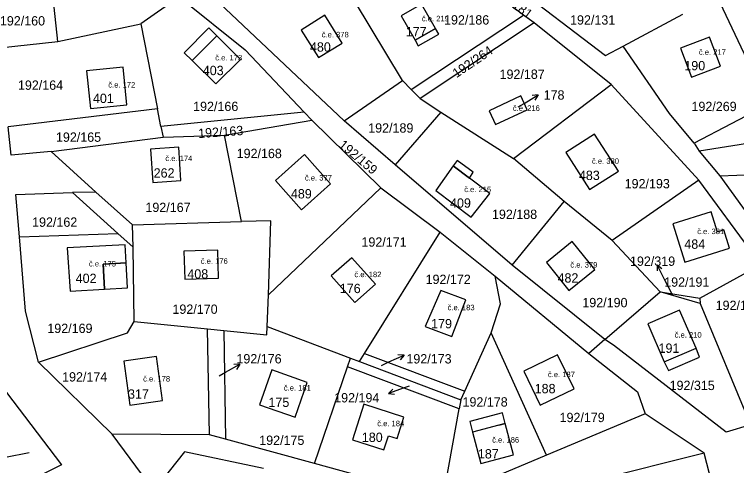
# Model space of a CAD drawing. Extents: x -887272 to -880188, y -1026687 to -1021896.
# Drawn here: x -882333.3 to -882201.9, y -1024194 to -1024111.9 of the extents above; entities that cross this region are included whole.
import ezdxf

# ---------------------------------------------------------------- set-up
doc = ezdxf.new("R2010")
doc.units = 0
for name, color, linetype in [('Definiční body', 7, 'Continuous'), ('Hranice parcel', 7, 'Continuous'), ('Parcelní čísla', 7, 'Continuous'), ('Polygon budovy', 7, 'Continuous'), ('Pop  PČ popisy', 7, 'Continuous'), ('Vnitřní kresba', 7, 'Continuous')]:
    doc.layers.add(name, color=color, linetype=linetype)

msp = doc.modelspace()

# ---------------------------------------------------------------- linework, layer by layer
at = {"layer": 'Hranice parcel'}
for p, q in [((-882240.6, -1024111.96), (-882256.19, -1024100.43)), ((-882325.37, -1024116.79), (-882326.44, -1024106.78)), ((-882273.27, -1024131.24), (-882298.33, -1024107.54)), ((-882303.23, -1024108.62), (-882310.26, -1024113.56)), ((-882262.64, -1024123.91), (-882271.37, -1024109.4)), ((-882261.07, -1024125.53), (-882240.6, -1024111.96)), ((-882238.67, -1024113.39), (-882240.6, -1024111.96)), ((-882222.5, -1024117.62), (-882211.61, -1024111.8)), ((-882325.37, -1024116.79), (-882310.26, -1024113.56)), ((-882310.26, -1024113.56), (-882307.23, -1024129.06)), ((-882238.67, -1024113.39), (-882259.45, -1024127.19)), ((-882224.7, -1024124.59), (-882238.67, -1024113.39)), ((-882336.02, -1024117.94), (-882325.37, -1024116.79)), ((-882273.27, -1024131.24), (-882262.64, -1024123.91)), ((-882262.64, -1024123.91), (-882261.07, -1024125.53)), ((-882242.43, -1024138.12), (-882224.7, -1024124.59)), ((-882224.7, -1024124.59), (-882208.75, -1024142.05)), ((-882259.45, -1024127.19), (-882261.07, -1024125.53)), ((-882259.45, -1024127.19), (-882255.64, -1024129.63)), ((-882307.23, -1024129.06), (-882334.41, -1024132.3)), ((-882306.6, -1024132.25), (-882307.23, -1024129.06)), ((-882280.53, -1024129.66), (-882306.6, -1024132.25)), ((-882280.53, -1024129.66), (-882279.12, -1024131.14)), ((-882255.64, -1024129.63), (-882263.95, -1024139.24)), ((-882255.64, -1024129.63), (-882242.43, -1024138.12)), ((-882295.03, -1024133.84), (-882279.12, -1024131.14)), ((-882279.12, -1024131.14), (-882266.59, -1024143.44)), ((-882263.95, -1024139.24), (-882273.27, -1024131.24)), ((-882306.6, -1024132.25), (-882306.22, -1024134.21)), ((-882306.22, -1024134.21), (-882295.03, -1024133.84)), ((-882291.94, -1024149.59), (-882295.03, -1024133.84)), ((-882190.49, -1024133.91), (-882208.64, -1024136.73)), ((-882326.6, -1024136.81), (-882306.22, -1024134.21)), ((-882209.58, -1024135.28), (-882208.64, -1024136.73)), ((-882208.64, -1024136.73), (-882204.92, -1024141.27)), ((-882242.67, -1024157.52), (-882263.95, -1024139.24)), ((-882233.24, -1024145.95), (-882242.43, -1024138.12)), ((-882204.92, -1024141.27), (-882175.35, -1024139.88)), ((-882204.92, -1024141.27), (-882191.8, -1024159.41)), ((-882208.75, -1024142.05), (-882224.52, -1024153.03)), ((-882197.43, -1024157.42), (-882208.75, -1024142.05)), ((-882266.59, -1024143.44), (-882287.05, -1024162.93)), ((-882266.59, -1024143.44), (-882255.81, -1024151.5)), ((-882242.67, -1024157.52), (-882233.24, -1024145.95)), ((-882224.52, -1024153.03), (-882233.24, -1024145.95)), ((-882311.75, -1024150.18), (-882291.94, -1024149.59)), ((-882286.58, -1024149.42), (-882291.94, -1024149.59)), ((-882287.05, -1024162.93), (-882286.58, -1024149.42)), ((-882311.68, -1024154.26), (-882311.75, -1024150.18)), ((-882332.34, -1024152.38), (-882314.45, -1024151.74)), ((-882314.45, -1024151.74), (-882311.68, -1024154.26)), ((-882269.58, -1024173.58), (-882255.81, -1024151.5)), ((-882255.81, -1024151.5), (-882245.77, -1024159.53)), ((-882231.74, -1024153.22), (-882236.46, -1024157.01)), ((-882215.75, -1024162.36), (-882224.52, -1024153.03)), ((-882311.45, -1024167.77), (-882311.68, -1024154.26)), ((-882225.84, -1024171.07), (-882242.67, -1024157.52)), ((-882208.53, -1024163.52), (-882197.43, -1024157.42)), ((-882245.77, -1024159.53), (-882228.75, -1024173.58)), ((-882287.25, -1024168.71), (-882287.05, -1024162.93)), ((-882225.84, -1024171.07), (-882215.75, -1024162.36)), ((-882215.75, -1024162.36), (-882208.53, -1024163.52)), ((-882208.46, -1024164.48), (-882215.75, -1024162.36)), ((-882208.53, -1024163.52), (-882208.46, -1024164.48)), ((-882208.46, -1024164.48), (-882199.3, -1024186.6)), ((-882311.45, -1024167.77), (-882298.11, -1024169.12)), ((-882298.11, -1024169.12), (-882295.13, -1024169.42)), ((-882297.75, -1024188.41), (-882298.11, -1024169.12)), ((-882295.13, -1024169.42), (-882294.85, -1024189.2)), ((-882287.25, -1024168.71), (-882272.13, -1024174.43)), ((-882251.31, -1024180.47), (-882246.53, -1024169.84)), ((-882236.46, -1024192.13), (-882246.53, -1024169.84)), ((-882225.84, -1024171.07), (-882228.75, -1024173.58)), ((-882272.67, -1024176.01), (-882272.13, -1024174.43)), ((-882272.13, -1024174.43), (-882270.49, -1024175.04)), ((-882270.49, -1024175.04), (-882269.58, -1024173.58)), ((-882269.58, -1024173.58), (-882251.31, -1024180.47)), ((-882315.45, -1024188.28), (-882328.87, -1024175.2)), ((-882278.63, -1024193.63), (-882272.67, -1024176.01)), ((-882252.31, -1024183.68), (-882272.67, -1024176.01)), ((-882270.49, -1024175.04), (-882252.01, -1024182.03)), ((-882252.01, -1024182.03), (-882251.31, -1024180.47)), ((-882252.01, -1024182.03), (-882252.31, -1024183.68)), ((-882255.25, -1024200.01), (-882252.31, -1024183.68)), ((-882218.48, -1024184.59), (-882236.46, -1024192.13)), ((-882207.74, -1024191.74), (-882218.48, -1024184.59)), ((-882297.75, -1024188.41), (-882315.45, -1024188.28)), ((-882307.87, -1024198.55), (-882315.45, -1024188.28)), ((-882294.85, -1024189.2), (-882297.75, -1024188.41)), ((-882278.63, -1024193.63), (-882294.85, -1024189.2)), ((-882207.74, -1024191.74), (-882227.58, -1024196.72)), ((-882204.37, -1024205.08), (-882207.74, -1024191.74)), ((-882236.46, -1024192.13), (-882255.25, -1024200.01)), ((-882255.25, -1024200.01), (-882278.63, -1024193.63))]:
    msp.add_line(p, q, dxfattribs=at)
for points in [[(-882243.24, -1024105.91), (-882225.71, -1024119.34), (-882222.5, -1024117.62)], [(-882303.23, -1024108.62), (-882291.29, -1024118.32), (-882280.53, -1024129.66)], [(-882205.42, -1024108.48), (-882196.11, -1024128.27), (-882209.58, -1024135.28)], [(-882259.17, -1024109.96), (-882262.9, -1024112.1), (-882260.34, -1024116.56), (-882259.77, -1024117.56), (-882256.04, -1024115.42), (-882256.61, -1024114.42), (-882259.17, -1024109.96)], [(-882276.8, -1024112.01), (-882281.11, -1024114.74), (-882277.9, -1024119.72)], [(-882277.9, -1024119.72), (-882273.64, -1024117.11), (-882276.8, -1024112.01)], [(-882302.36, -1024118.83), (-882300.9, -1024120.27), (-882296.63, -1024124.49), (-882292.12, -1024120.06), (-882296.44, -1024115.78), (-882297.91, -1024114.32), (-882302.36, -1024118.83)], [(-882206.79, -1024115.98), (-882212.07, -1024117.99), (-882210.06, -1024123.27), (-882204.78, -1024121.26), (-882206.79, -1024115.98)], [(-882209.58, -1024135.28), (-882214.07, -1024129.89), (-882222.5, -1024117.62)], [(-882320.14, -1024122.11), (-882319.42, -1024128.99), (-882312.79, -1024128.33), (-882313.5, -1024121.45), (-882320.14, -1024122.11)], [(-882239.95, -1024129.23), (-882241.14, -1024126.7), (-882246.89, -1024129.39), (-882245.73, -1024131.88), (-882239.95, -1024129.23)], [(-882326.6, -1024136.81), (-882333.83, -1024137.51), (-882334.41, -1024132.3)], [(-882232.9, -1024136.97), (-882228.63, -1024143.71), (-882223.31, -1024140.39), (-882227.68, -1024133.67), (-882232.9, -1024136.97)], [(-882308.5, -1024136.4), (-882308.08, -1024142.48), (-882302.95, -1024142.12), (-882303.37, -1024136.04), (-882308.5, -1024136.4)], [(-882311.75, -1024150.18), (-882318.47, -1024144.2), (-882326.6, -1024136.81)], [(-882280.47, -1024137.35), (-882285.76, -1024142.1), (-882281.04, -1024147.43), (-882275.73, -1024142.69), (-882280.47, -1024137.35)], [(-882250.44, -1024141.66), (-882249.76, -1024140.6), (-882252.7, -1024138.44), (-882253.4, -1024139.42), (-882256.6, -1024143.89), (-882250.16, -1024148.8), (-882246.78, -1024144.44), (-882250.44, -1024141.66)], [(-882332.34, -1024152.38), (-882332.98, -1024144.63), (-882322.66, -1024144.28), (-882314.45, -1024151.74)], [(-882204.16, -1024151.1), (-882205.35, -1024151.48), (-882206.5, -1024147.81), (-882213.47, -1024149.97), (-882211.29, -1024156.96), (-882203.13, -1024154.43), (-882204.16, -1024151.1)], [(-882328.87, -1024175.2), (-882331.22, -1024165.89), (-882332.34, -1024152.38)], [(-882236.46, -1024157.01), (-882232.35, -1024162.12), (-882227.63, -1024158.33), (-882231.74, -1024153.22)], [(-882313.11, -1024153.8), (-882323.69, -1024154.38), (-882323.12, -1024162.22), (-882316.86, -1024161.9), (-882312.69, -1024161.65), (-882312.93, -1024157.1), (-882313.11, -1024153.8)], [(-882302.42, -1024154.94), (-882302.27, -1024160.04), (-882296.12, -1024159.86), (-882296.27, -1024154.76), (-882302.42, -1024154.94)], [(-882271.32, -1024164.34), (-882267.54, -1024160.98), (-882271.88, -1024156.18), (-882275.64, -1024159.48), (-882271.32, -1024164.34)], [(-882246.53, -1024169.84), (-882244.78, -1024164.57), (-882245.77, -1024159.53)], [(-882253.64, -1024170.5), (-882251.12, -1024163.82), (-882255.66, -1024162.1), (-882258.5, -1024168.66), (-882253.64, -1024170.5)], [(-882215.03, -1024175.11), (-882214.26, -1024176.72), (-882208.6, -1024174.25), (-882209.22, -1024172.63), (-882212.26, -1024165.7), (-882218.01, -1024168.17), (-882215.03, -1024175.11)], [(-882328.87, -1024175.2), (-882312.69, -1024169.82), (-882311.45, -1024167.77)], [(-882295.13, -1024169.42), (-882287.3, -1024170.21), (-882287.25, -1024168.71)], [(-882199.3, -1024186.6), (-882203.76, -1024187.9), (-882224.27, -1024172.09), (-882225.84, -1024171.07)], [(-882313.37, -1024174.98), (-882312.24, -1024183), (-882306.31, -1024182.16), (-882307.43, -1024174.15), (-882313.37, -1024174.98)], [(-882237.58, -1024183.02), (-882231.43, -1024180.03), (-882234.46, -1024173.84), (-882240.59, -1024176.84), (-882237.58, -1024183.02)], [(-882228.75, -1024173.58), (-882219.88, -1024180.56), (-882218.48, -1024184.59)], [(-882279.97, -1024178.86), (-882286.44, -1024176.59), (-882288.66, -1024182.92), (-882282.18, -1024185.19), (-882279.97, -1024178.86)], [(-882334.7, -1024180.71), (-882324.68, -1024193.85), (-882333.83, -1024198.49)], [(-882263.59, -1024189.1), (-882262.38, -1024185.19), (-882269.68, -1024182.83), (-882271.77, -1024189.3), (-882266.04, -1024191.15), (-882265.21, -1024188.58), (-882263.59, -1024189.1)], [(-882244.46, -1024184.4), (-882250.4, -1024185.99), (-882249.88, -1024187.94), (-882248.36, -1024193.62), (-882242.42, -1024192.03), (-882243.94, -1024186.35), (-882244.46, -1024184.4)], [(-882287.91, -1024194.55), (-882302.33, -1024191.49), (-882307.87, -1024198.55)]]:
    msp.add_lwpolyline(points, dxfattribs=at)
at = {"layer": 'Polygon budovy'}
for points in [[(-882256.61, -1024114.42), (-882259.17, -1024109.96), (-882262.9, -1024112.1), (-882260.34, -1024116.56)], [(-882276.8, -1024112.01), (-882281.11, -1024114.74), (-882277.9, -1024119.72), (-882273.64, -1024117.11)], [(-882296.44, -1024115.78), (-882300.9, -1024120.27), (-882296.63, -1024124.49), (-882292.12, -1024120.06)], [(-882204.78, -1024121.26), (-882206.79, -1024115.98), (-882212.07, -1024117.99), (-882210.06, -1024123.27)], [(-882313.5, -1024121.45), (-882320.14, -1024122.11), (-882319.42, -1024128.99), (-882312.79, -1024128.33)], [(-882241.14, -1024126.7), (-882246.89, -1024129.39), (-882245.73, -1024131.88), (-882239.95, -1024129.23)], [(-882232.9, -1024136.97), (-882228.63, -1024143.71), (-882223.31, -1024140.39), (-882227.68, -1024133.67)], [(-882308.5, -1024136.4), (-882308.08, -1024142.48), (-882302.95, -1024142.12), (-882303.37, -1024136.04)], [(-882285.76, -1024142.1), (-882281.04, -1024147.43), (-882275.73, -1024142.69), (-882280.47, -1024137.35)], [(-882250.44, -1024141.66), (-882253.4, -1024139.42), (-882256.6, -1024143.89), (-882250.16, -1024148.8), (-882246.78, -1024144.44)], [(-882203.13, -1024154.43), (-882204.16, -1024151.1), (-882205.35, -1024151.48), (-882206.5, -1024147.81), (-882213.47, -1024149.97), (-882211.29, -1024156.96)], [(-882231.74, -1024153.22), (-882236.46, -1024157.01), (-882232.35, -1024162.12), (-882227.63, -1024158.33)], [(-882316.86, -1024161.9), (-882317.12, -1024157.32), (-882312.93, -1024157.1), (-882313.11, -1024153.8), (-882323.69, -1024154.38), (-882323.12, -1024162.22)], [(-882302.42, -1024154.94), (-882302.27, -1024160.04), (-882296.12, -1024159.86), (-882296.27, -1024154.76)], [(-882271.32, -1024164.34), (-882267.54, -1024160.98), (-882271.88, -1024156.18), (-882275.64, -1024159.48)], [(-882258.5, -1024168.66), (-882253.64, -1024170.5), (-882251.12, -1024163.82), (-882255.66, -1024162.1)], [(-882218.01, -1024168.17), (-882215.03, -1024175.11), (-882209.22, -1024172.63), (-882212.26, -1024165.7)], [(-882306.31, -1024182.16), (-882307.43, -1024174.15), (-882313.37, -1024174.98), (-882312.24, -1024183)], [(-882240.59, -1024176.84), (-882237.58, -1024183.02), (-882231.43, -1024180.03), (-882234.46, -1024173.84)], [(-882286.44, -1024176.59), (-882288.66, -1024182.92), (-882282.18, -1024185.19), (-882279.97, -1024178.86)], [(-882266.04, -1024191.15), (-882265.21, -1024188.58), (-882263.59, -1024189.1), (-882262.38, -1024185.19), (-882269.68, -1024182.83), (-882271.77, -1024189.3)], [(-882243.94, -1024186.35), (-882245.1, -1024186.66), (-882249.88, -1024187.94), (-882248.36, -1024193.62), (-882242.42, -1024192.03)]]:
    msp.add_lwpolyline(points, close=True, dxfattribs=at)
at = {"layer": 'Pop  PČ popisy'}
for p, q in [((-882240.53, -1024128.07), (-882237.96, -1024126.52)), ((-882237.96, -1024126.52), (-882239.07, -1024126.61)), ((-882237.96, -1024126.52), (-882238.56, -1024127.47)), ((-882241.58, -1024128.7), (-882240.53, -1024128.07)), ((-882214.97, -1024160.12), (-882216.33, -1024157.45)), ((-882216.33, -1024157.45), (-882215.43, -1024158.11)), ((-882216.33, -1024157.45), (-882216.32, -1024158.57)), ((-882213.53, -1024162.91), (-882214.97, -1024160.12)), ((-882265.1, -1024175.13), (-882262.36, -1024173.91)), ((-882262.36, -1024173.91), (-882263.48, -1024173.86)), ((-882262.36, -1024173.91), (-882263.07, -1024174.77)), ((-882294.85, -1024177.02), (-882292.22, -1024175.57)), ((-882292.22, -1024175.57), (-882293.34, -1024175.61)), ((-882292.22, -1024175.57), (-882292.86, -1024176.49)), ((-882266.48, -1024175.76), (-882265.1, -1024175.13)), ((-882296.03, -1024177.68), (-882294.85, -1024177.02)), ((-882262.36, -1024179.87), (-882265.18, -1024180.9)), ((-882261.43, -1024179.53), (-882262.36, -1024179.87)), ((-882265.18, -1024180.9), (-882264.41, -1024180.08)), ((-882265.18, -1024180.9), (-882264.07, -1024181.02)), ((-882330.55, -1024191.69), (-882334.87, -1024192.55))]:
    msp.add_line(p, q, dxfattribs=at)
at = {"layer": 'Vnitřní kresba'}
for p, q in [((-882256.61, -1024114.42), (-882260.34, -1024116.56)), ((-882300.9, -1024120.27), (-882296.44, -1024115.78)), ((-882253.4, -1024139.42), (-882250.44, -1024141.66)), ((-882318.47, -1024144.2), (-882322.66, -1024144.28)), ((-882312.93, -1024157.1), (-882317.12, -1024157.32)), ((-882317.12, -1024157.32), (-882316.86, -1024161.9)), ((-882215.03, -1024175.11), (-882209.22, -1024172.63)), ((-882245.1, -1024186.66), (-882243.94, -1024186.35)), ((-882245.1, -1024186.66), (-882249.88, -1024187.94))]:
    msp.add_line(p, q, dxfattribs=at)

# ---------------------------------------------------------------- texts
at = {"layer": 'Definiční body'}
for s, p in [('č.e. 219', (-882259.12, -1024113.11)), ('č.e. 378', (-882277.34, -1024116.03)), ('č.e. 217', (-882208.71, -1024119.21)), ('č.e. 173', (-882296.72, -1024120.23)), ('č.e. 172', (-882316.18, -1024125.17)), ('č.e. 216', (-882242.56, -1024129.42)), ('č.e. 174', (-882305.79, -1024138.56)), ('č.e. 380', (-882228.17, -1024139.06)), ('č.e. 377', (-882280.4, -1024142.1)), ('č.e. 215', (-882251.42, -1024144.21)), ('č.e. 381', (-882209.02, -1024151.86)), ('č.e. 176', (-882299.35, -1024157.27)), ('č.e. 175', (-882319.7, -1024157.75)), ('č.e. 379', (-882232.1, -1024157.95)), ('č.e. 182', (-882271.39, -1024159.7)), ('č.e. 183', (-882254.44, -1024165.72)), ('č.e. 210', (-882213.12, -1024170.71)), ('č.e. 187', (-882236.18, -1024177.91)), ('č.e. 178', (-882309.84, -1024178.7)), ('č.e. 181', (-882284.24, -1024180.36)), ('č.e. 184', (-882267.24, -1024186.84)), ('č.e. 186', (-882246.33, -1024189.82))]:
    msp.add_text(s, height=1, dxfattribs=at).set_placement(p)
at = {"layer": 'Parcelní čísla'}
for s, rotation, p in [('192/181', 324, (-882246.42, -1024107.91)), ('192/264', 34, (-882252.82, -1024123.47)), ('192/163', 4, (-882299.76, -1024134.38)), ('192/159', 320, (-882274.39, -1024135.84))]:
    msp.add_text(s, height=1.7, rotation=rotation, dxfattribs=at).set_placement(p)
for s, p in [('192/160', (-882335.9, -1024113.87)), ('192/186', (-882255.08, -1024113.7)), ('192/131', (-882232.15, -1024113.71)), ('177', (-882262.05, -1024115.84)), ('480', (-882279.48, -1024118.63)), ('190', (-882211.36, -1024122.03)), ('403', (-882298.98, -1024122.91)), ('192/187', (-882244.98, -1024123.59)), ('192/164', (-882332.62, -1024125.58)), ('178', (-882236.96, -1024127.37)), ('401', (-882318.97, -1024127.99)), ('192/166', (-882300.74, -1024129.45)), ('192/269', (-882210.06, -1024129.46)), ('192/189', (-882268.88, -1024133.38)), ('192/165', (-882325.7, -1024135.05)), ('192/168', (-882292.82, -1024138.02)), ('262', (-882307.92, -1024141.57)), ('483', (-882230.54, -1024142.01)), ('192/193', (-882222.22, -1024143.53)), ('489', (-882282.95, -1024145.36)), ('409', (-882253.99, -1024147.05)), ('192/167', (-882309.42, -1024147.84)), ('192/188', (-882246.36, -1024149.1)), ('192/162', (-882330.04, -1024150.53)), ('192/171', (-882270.11, -1024154.15)), ('484', (-882211.36, -1024154.53)), ('192/319', (-882221.25, -1024157.64)), ('408', (-882301.79, -1024159.96)), ('482', (-882234.43, -1024160.69)), ('402', (-882322.11, -1024160.76)), ('192/172', (-882258.44, -1024160.95)), ('192/191', (-882215.02, -1024161.45)), ('176', (-882274.05, -1024162.6)), ('192/190', (-882229.92, -1024165.18)), ('192/192', (-882205.66, -1024165.68)), ('192/170', (-882304.5, -1024166.38)), ('192/169', (-882327.27, -1024169.87)), ('179', (-882257.43, -1024169.02)), ('191', (-882216.05, -1024173.48)), ('192/176', (-882292.86, -1024175.41)), ('192/173', (-882261.93, -1024175.42)), ('192/174', (-882324.58, -1024178.71)), ('192/315', (-882214.04, -1024180.26)), ('188', (-882238.59, -1024180.84)), ('317', (-882312.59, -1024181.83)), ('192/194', (-882275.07, -1024182.51)), ('175', (-882287.03, -1024183.34)), ('192/178', (-882251.72, -1024183.27)), ('192/179', (-882234.06, -1024186.1)), ('192/175', (-882288.71, -1024190.25)), ('180', (-882270.04, -1024189.71)), ('187', (-882248.92, -1024192.72))]:
    msp.add_text(s, height=1.7, dxfattribs=at).set_placement(p)

doc.saveas('drawing.dxf')
